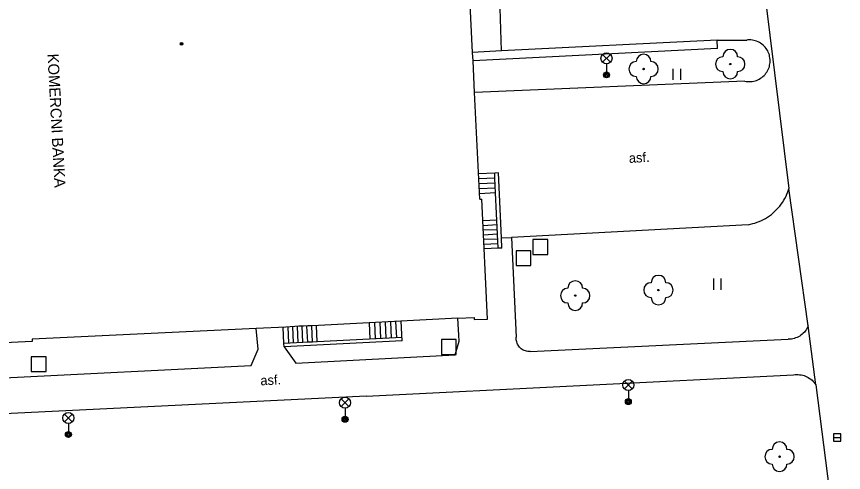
# Model space of a CAD drawing. Extents: x -641829 to -641525, y -1114855 to -1114359.
# Drawn here: x -641782.2 to -641726.2, y -1114487.2 to -1114456.3 of the extents above; entities that cross this region are included whole.
import ezdxf

# ---------------------------------------------------------------- set-up
doc = ezdxf.new("R2010")
doc.units = 0
for name, color, linetype in [('Vrstva 10', 7, 'Continuous'), ('Vrstva 11', 7, 'Continuous'), ('Vrstva 22', 7, 'Continuous'), ('Vrstva 26', 7, 'Continuous'), ('Vrstva 27', 7, 'Continuous'), ('Vrstva 33', 7, 'Continuous'), ('Vrstva 36', 7, 'Continuous'), ('Vrstva 39', 7, 'Continuous'), ('Vrstva 40', 7, 'Continuous'), ('Vrstva 41', 7, 'Continuous'), ('Vrstva 5', 7, 'Continuous')]:
    doc.layers.add(name, color=color, linetype=linetype)

msp = doc.modelspace()

# ---------------------------------------------------------------- linework, layer by layer
at = {"layer": 'Vrstva 10'}
for p, q in [((-641749.32, -1114458.63), (-641749.83, -1114441.84)), ((-641731.98, -1114450.77), (-641729.84, -1114467.94)), ((-641734.71, -1114457.89), (-641732.69, -1114457.89)), ((-641732.62, -1114457.88), (-641732.69, -1114457.89)), ((-641732.52, -1114457.88), (-641732.62, -1114457.88)), ((-641732.42, -1114457.88), (-641732.52, -1114457.88)), ((-641732.32, -1114457.9), (-641732.42, -1114457.88)), ((-641732.22, -1114457.91), (-641732.32, -1114457.9)), ((-641732.12, -1114457.94), (-641732.22, -1114457.91)), ((-641732.03, -1114457.97), (-641732.12, -1114457.94)), ((-641731.93, -1114458.01), (-641732.03, -1114457.97)), ((-641731.84, -1114458.06), (-641731.93, -1114458.01)), ((-641731.76, -1114458.11), (-641731.84, -1114458.06)), ((-641731.68, -1114458.17), (-641731.76, -1114458.11)), ((-641731.6, -1114458.23), (-641731.68, -1114458.17)), ((-641731.52, -1114458.3), (-641731.6, -1114458.23)), ((-641731.45, -1114458.37), (-641731.52, -1114458.3)), ((-641731.39, -1114458.45), (-641731.45, -1114458.37)), ((-641731.34, -1114458.53), (-641731.39, -1114458.45)), ((-641731.28, -1114458.62), (-641731.34, -1114458.53)), ((-641731.24, -1114458.71), (-641731.28, -1114458.62)), ((-641731.2, -1114458.81), (-641731.24, -1114458.71)), ((-641731.17, -1114458.9), (-641731.2, -1114458.81)), ((-641731.15, -1114459), (-641731.17, -1114458.9)), ((-641731.13, -1114459.1), (-641731.15, -1114459)), ((-641731.15, -1114459.6), (-641731.13, -1114459.5)), ((-641731.12, -1114459.2), (-641731.13, -1114459.1)), ((-641731.13, -1114459.5), (-641731.12, -1114459.4)), ((-641731.11, -1114459.3), (-641731.12, -1114459.2)), ((-641731.12, -1114459.4), (-641731.11, -1114459.3)), ((-641731.4, -1114460.14), (-641731.34, -1114460.06)), ((-641731.34, -1114460.06), (-641731.29, -1114459.98)), ((-641731.29, -1114459.98), (-641731.24, -1114459.89)), ((-641731.24, -1114459.89), (-641731.2, -1114459.79)), ((-641731.2, -1114459.79), (-641731.17, -1114459.7)), ((-641731.17, -1114459.7), (-641731.15, -1114459.6)), ((-641732.23, -1114460.67), (-641732.14, -1114460.65)), ((-641732.14, -1114460.65), (-641732.04, -1114460.62)), ((-641732.04, -1114460.62), (-641731.95, -1114460.58)), ((-641731.95, -1114460.58), (-641731.86, -1114460.53)), ((-641731.86, -1114460.53), (-641731.77, -1114460.48)), ((-641731.77, -1114460.48), (-641731.69, -1114460.43)), ((-641731.69, -1114460.43), (-641731.61, -1114460.36)), ((-641731.61, -1114460.36), (-641731.53, -1114460.3)), ((-641731.53, -1114460.3), (-641731.46, -1114460.22)), ((-641731.46, -1114460.22), (-641731.4, -1114460.14)), ((-641732.83, -1114460.67), (-641751.14, -1114461.43)), ((-641732.83, -1114460.67), (-641732.73, -1114460.69)), ((-641732.73, -1114460.69), (-641732.63, -1114460.7)), ((-641732.63, -1114460.7), (-641732.53, -1114460.7)), ((-641732.53, -1114460.7), (-641732.43, -1114460.7)), ((-641732.43, -1114460.7), (-641732.33, -1114460.69)), ((-641732.33, -1114460.69), (-641732.23, -1114460.67)), ((-641729.87, -1114468.02), (-641729.84, -1114467.94)), ((-641728.54, -1114477.24), (-641729.84, -1114467.94)), ((-641730.12, -1114468.61), (-641730.04, -1114468.46)), ((-641730.04, -1114468.46), (-641729.98, -1114468.32)), ((-641729.98, -1114468.32), (-641729.92, -1114468.17)), ((-641729.92, -1114468.17), (-641729.87, -1114468.02)), ((-641730.47, -1114469.13), (-641730.37, -1114469.01)), ((-641730.37, -1114469.01), (-641730.28, -1114468.88)), ((-641730.28, -1114468.88), (-641730.19, -1114468.74)), ((-641730.19, -1114468.74), (-641730.12, -1114468.61)), ((-641731.03, -1114469.69), (-641730.91, -1114469.59)), ((-641730.91, -1114469.59), (-641730.79, -1114469.48)), ((-641730.79, -1114469.48), (-641730.68, -1114469.37)), ((-641730.68, -1114469.37), (-641730.57, -1114469.25)), ((-641730.57, -1114469.25), (-641730.47, -1114469.13)), ((-641732, -1114470.23), (-641731.85, -1114470.17)), ((-641731.85, -1114470.17), (-641731.7, -1114470.11)), ((-641731.7, -1114470.11), (-641731.56, -1114470.03)), ((-641731.56, -1114470.03), (-641731.42, -1114469.96)), ((-641731.42, -1114469.96), (-641731.29, -1114469.87)), ((-641731.29, -1114469.87), (-641731.16, -1114469.78)), ((-641731.16, -1114469.78), (-641731.03, -1114469.69)), ((-641732.61, -1114470.39), (-641748.63, -1114471.25)), ((-641732.61, -1114470.39), (-641732.45, -1114470.36)), ((-641732.45, -1114470.36), (-641732.3, -1114470.32)), ((-641732.3, -1114470.32), (-641732.15, -1114470.28)), ((-641732.15, -1114470.28), (-641732, -1114470.23)), ((-641749.32, -1114471.28), (-641748.63, -1114471.25)), ((-641728.02, -1114481.24), (-641728.54, -1114477.24)), ((-641728.02, -1114481.24), (-641726.15, -1114495.75))]:
    msp.add_line(p, q, dxfattribs=at)
at = {"layer": 'Vrstva 11'}
for p, q in [((-641734.71, -1114457.89), (-641749.32, -1114458.63)), ((-641734.68, -1114458.45), (-641734.71, -1114457.89)), ((-641749.32, -1114458.63), (-641751.27, -1114458.73)), ((-641734.68, -1114458.45), (-641751.24, -1114459.29)), ((-641749.76, -1114467.23), (-641750.85, -1114467.28)), ((-641749.32, -1114471.28), (-641749.52, -1114466.88)), ((-641749.74, -1114467.57), (-641750.83, -1114467.62)), ((-641749.73, -1114467.91), (-641750.82, -1114467.96)), ((-641749.71, -1114468.24), (-641750.8, -1114468.3)), ((-641749.62, -1114470.09), (-641750.57, -1114470.14)), ((-641749.61, -1114470.41), (-641750.56, -1114470.46)), ((-641749.59, -1114470.73), (-641750.54, -1114470.77)), ((-641749.58, -1114471.04), (-641750.53, -1114471.09)), ((-641749.29, -1114471.98), (-641749.32, -1114471.28)), ((-641748.63, -1114471.25), (-641748.31, -1114478.01)), ((-641749.56, -1114471.36), (-641750.51, -1114471.4)), ((-641749.55, -1114471.68), (-641750.5, -1114471.72)), ((-641752.21, -1114477.87), (-641752.28, -1114476.73)), ((-641765.79, -1114478.81), (-641765.94, -1114477.42)), ((-641763.72, -1114478.42), (-641763.77, -1114477.31)), ((-641763.4, -1114478.4), (-641763.45, -1114477.29)), ((-641763.08, -1114478.39), (-641763.13, -1114477.28)), ((-641762.76, -1114478.37), (-641762.81, -1114477.26)), ((-641762.44, -1114478.35), (-641762.49, -1114477.25)), ((-641762.12, -1114478.34), (-641762.17, -1114477.23)), ((-641761.8, -1114478.32), (-641761.85, -1114477.21)), ((-641758.2, -1114478.14), (-641758.26, -1114477.03)), ((-641757.84, -1114478.12), (-641757.9, -1114477.01)), ((-641757.48, -1114478.1), (-641757.54, -1114477)), ((-641757.13, -1114478.09), (-641757.18, -1114476.98)), ((-641756.77, -1114478.07), (-641756.82, -1114476.96)), ((-641756.41, -1114478.05), (-641756.47, -1114476.94)), ((-641756.04, -1114478.26), (-641756.11, -1114476.92)), ((-641728.63, -1114477.42), (-641728.68, -1114477.5)), ((-641728.58, -1114477.33), (-641728.63, -1114477.42)), ((-641728.54, -1114477.24), (-641728.58, -1114477.33)), ((-641752.19, -1114478.27), (-641752.21, -1114477.87)), ((-641748.31, -1114478.1), (-641748.31, -1114478.01)), ((-641729.29, -1114478.02), (-641729.39, -1114478.06)), ((-641729.2, -1114477.98), (-641729.29, -1114478.02)), ((-641729.11, -1114477.93), (-641729.2, -1114477.98)), ((-641729.03, -1114477.87), (-641729.11, -1114477.93)), ((-641728.95, -1114477.81), (-641729.03, -1114477.87)), ((-641728.88, -1114477.74), (-641728.95, -1114477.81)), ((-641728.8, -1114477.67), (-641728.88, -1114477.74)), ((-641728.74, -1114477.59), (-641728.8, -1114477.67)), ((-641728.68, -1114477.5), (-641728.74, -1114477.59)), ((-641756.04, -1114478.26), (-641764.03, -1114478.67)), ((-641752.45, -1114479.2), (-641752.19, -1114478.27)), ((-641748.31, -1114478.18), (-641748.31, -1114478.1)), ((-641748.3, -1114478.25), (-641748.31, -1114478.18)), ((-641748.28, -1114478.33), (-641748.3, -1114478.25)), ((-641748.25, -1114478.41), (-641748.28, -1114478.33)), ((-641748.22, -1114478.48), (-641748.25, -1114478.41)), ((-641748.18, -1114478.55), (-641748.22, -1114478.48)), ((-641748.14, -1114478.62), (-641748.18, -1114478.55)), ((-641747.37, -1114478.98), (-641729.89, -1114478.15)), ((-641729.78, -1114478.15), (-641729.89, -1114478.15)), ((-641729.68, -1114478.14), (-641729.78, -1114478.15)), ((-641729.58, -1114478.12), (-641729.68, -1114478.14)), ((-641729.48, -1114478.09), (-641729.58, -1114478.12)), ((-641729.39, -1114478.06), (-641729.48, -1114478.09)), ((-641766.27, -1114479.92), (-641765.79, -1114478.81)), ((-641764.03, -1114478.67), (-641763.25, -1114479.76)), ((-641748.09, -1114478.68), (-641748.14, -1114478.62)), ((-641748.03, -1114478.74), (-641748.09, -1114478.68)), ((-641747.97, -1114478.79), (-641748.03, -1114478.74)), ((-641747.91, -1114478.84), (-641747.97, -1114478.79)), ((-641747.84, -1114478.88), (-641747.91, -1114478.84)), ((-641747.77, -1114478.91), (-641747.84, -1114478.88)), ((-641747.69, -1114478.94), (-641747.77, -1114478.91)), ((-641747.61, -1114478.96), (-641747.69, -1114478.94)), ((-641747.53, -1114478.97), (-641747.61, -1114478.96)), ((-641747.45, -1114478.98), (-641747.53, -1114478.97)), ((-641747.37, -1114478.98), (-641747.45, -1114478.98)), ((-641763.25, -1114479.76), (-641752.45, -1114479.2)), ((-641798.58, -1114481.55), (-641766.27, -1114479.92)), ((-641758.49, -1114482), (-641729.54, -1114480.56)), ((-641729.54, -1114480.56), (-641729.42, -1114480.54)), ((-641729.42, -1114480.54), (-641729.32, -1114480.54)), ((-641729.32, -1114480.54), (-641729.22, -1114480.54)), ((-641729.22, -1114480.54), (-641729.12, -1114480.55)), ((-641729.12, -1114480.55), (-641729.01, -1114480.56)), ((-641729.01, -1114480.56), (-641728.91, -1114480.58)), ((-641728.91, -1114480.58), (-641728.81, -1114480.61)), ((-641728.81, -1114480.61), (-641728.72, -1114480.65)), ((-641728.72, -1114480.65), (-641728.62, -1114480.69)), ((-641728.62, -1114480.69), (-641728.53, -1114480.74)), ((-641728.53, -1114480.74), (-641728.45, -1114480.8)), ((-641728.45, -1114480.8), (-641728.36, -1114480.86)), ((-641728.36, -1114480.86), (-641728.28, -1114480.92)), ((-641728.28, -1114480.92), (-641728.21, -1114481)), ((-641728.21, -1114481), (-641728.14, -1114481.07)), ((-641728.14, -1114481.07), (-641728.08, -1114481.15)), ((-641728.08, -1114481.15), (-641728.02, -1114481.24)), ((-641758.49, -1114482), (-641797.98, -1114483.93))]:
    msp.add_line(p, q, dxfattribs=at)
for points in [[(-641749.52, -1114466.88), (-641749.77, -1114466.9), (-641750.87, -1114466.95)], [(-641749.54, -1114471.99), (-641749.58, -1114471.04), (-641749.71, -1114468.24), (-641749.76, -1114467.23), (-641749.77, -1114466.9)], [(-641749.29, -1114471.98), (-641749.54, -1114471.99), (-641750.48, -1114472.03)], [(-641764.03, -1114478.67), (-641764.05, -1114478.44), (-641764.1, -1114477.33)], [(-641756.05, -1114478.03), (-641761.8, -1114478.32), (-641762.12, -1114478.34), (-641762.44, -1114478.35), (-641762.76, -1114478.37), (-641764.05, -1114478.44)]]:
    msp.add_lwpolyline(points, dxfattribs=at)
at = {"layer": 'Vrstva 22'}
for centre in [(-641733.82, -1114459.52), (-641739.69, -1114459.85), (-641744.32, -1114475.19), (-641738.68, -1114474.82), (-641730.48, -1114486.1)]:
    msp.add_circle(centre, 0.05, dxfattribs=at)
for centre, start, end in [((-641739.69, -1114459.35), 0, 180), ((-641733.82, -1114459.02), 0, 180), ((-641740.19, -1114459.85), 90, 270), ((-641739.19, -1114459.85), 270, 90), ((-641734.32, -1114459.52), 90, 270), ((-641733.32, -1114459.52), 270, 90), ((-641733.82, -1114460.02), 180, 0), ((-641739.69, -1114460.35), 180, 0), ((-641738.68, -1114474.32), 0, 180), ((-641744.32, -1114474.69), 0, 180), ((-641739.18, -1114474.82), 90, 270), ((-641738.18, -1114474.82), 270, 90), ((-641744.82, -1114475.19), 90, 270), ((-641743.82, -1114475.19), 270, 90), ((-641744.32, -1114475.69), 180, 0), ((-641738.68, -1114475.32), 180, 0), ((-641730.48, -1114485.6), 0, 180), ((-641730.98, -1114486.1), 90, 270), ((-641729.98, -1114486.1), 270, 90), ((-641730.48, -1114486.6), 180, 0)]:
    msp.add_arc(centre, 0.5, start, end, dxfattribs=at)
at = {"layer": 'Vrstva 26'}
for points in [[(-641747.18, -1114472.4), (-641746.18, -1114472.4), (-641746.18, -1114471.4), (-641747.18, -1114471.4)], [(-641748.33, -1114473.15), (-641747.33, -1114473.15), (-641747.33, -1114472.15), (-641748.33, -1114472.15)], [(-641753.38, -1114479.17), (-641752.38, -1114479.17), (-641752.38, -1114478.17), (-641753.38, -1114478.17)], [(-641781.16, -1114480.33), (-641780.16, -1114480.33), (-641780.16, -1114479.33), (-641781.16, -1114479.33)]]:
    msp.add_lwpolyline(points, close=True, dxfattribs=at)
at = {"layer": 'Vrstva 27'}
msp.add_line((-641726.83, -1114484.8), (-641726.33, -1114484.8), dxfattribs=at)
msp.add_lwpolyline([(-641726.83, -1114485.05), (-641726.33, -1114485.05), (-641726.33, -1114484.55), (-641726.83, -1114484.55)], close=True, dxfattribs=at)
at = {"layer": 'Vrstva 33'}
for p, q in [((-641742.464, -1114459.39), (-641741.936, -1114458.86)), ((-641742.464, -1114458.86), (-641741.936, -1114459.39)), ((-641742.2, -1114459.5), (-641742.2, -1114460.25)), ((-641740.986, -1114481.51), (-641740.454, -1114480.98)), ((-641740.986, -1114480.98), (-641740.454, -1114481.51)), ((-641740.72, -1114481.62), (-641740.72, -1114482.37)), ((-641760.176, -1114482.71), (-641759.644, -1114482.18)), ((-641760.176, -1114482.18), (-641759.644, -1114482.71)), ((-641759.91, -1114482.82), (-641759.91, -1114483.57)), ((-641778.914, -1114483.74), (-641778.386, -1114483.21)), ((-641778.914, -1114483.21), (-641778.386, -1114483.74)), ((-641778.65, -1114483.85), (-641778.65, -1114484.6))]:
    msp.add_line(p, q, dxfattribs=at)
for centre, radius in [((-641742.2, -1114459.125), 0.375), ((-641742.2, -1114460.25), 0.2), ((-641742.2, -1114460.25), 0.145), ((-641742.2, -1114460.25), 0.0876), ((-641740.72, -1114481.245), 0.375), ((-641759.91, -1114482.445), 0.375), ((-641740.72, -1114482.37), 0.2), ((-641740.72, -1114482.37), 0.145), ((-641740.72, -1114482.37), 0.0876), ((-641778.65, -1114483.475), 0.375), ((-641759.91, -1114483.57), 0.2), ((-641759.91, -1114483.57), 0.145), ((-641759.91, -1114483.57), 0.0876), ((-641778.65, -1114484.6), 0.2), ((-641778.65, -1114484.6), 0.145), ((-641778.65, -1114484.6), 0.0876)]:
    msp.add_circle(centre, radius, dxfattribs=at)
at = {"layer": 'Vrstva 36'}
for p, q in [((-641737.674, -1114460.582), (-641737.674, -1114459.834)), ((-641737.174, -1114460.582), (-641737.174, -1114459.834)), ((-641734.924, -1114474.794), (-641734.924, -1114474.042)), ((-641734.424, -1114474.794), (-641734.424, -1114474.042))]:
    msp.add_line(p, q, dxfattribs=at)
at = {"layer": 'Vrstva 39'}
for radius in [0.09, 0.0398]:
    msp.add_circle((-641770.98, -1114458.14), radius, dxfattribs=at)
at = {"layer": 'Vrstva 5'}
for p, q in [((-641751.27, -1114458.73), (-641752.17, -1114440.22)), ((-641751.24, -1114459.29), (-641751.27, -1114458.73)), ((-641751.14, -1114461.43), (-641751.24, -1114459.29)), ((-641750.78, -1114468.67), (-641751.14, -1114461.43)), ((-641750.78, -1114468.67), (-641750.64, -1114468.66)), ((-641750.26, -1114476.78), (-641750.64, -1114468.66)), ((-641752.28, -1114476.73), (-641762.13, -1114477.23)), ((-641752.28, -1114476.73), (-641751.17, -1114476.68)), ((-641751.17, -1114476.68), (-641751.16, -1114476.82)), ((-641751.16, -1114476.82), (-641750.26, -1114476.78)), ((-641765.94, -1114477.42), (-641781.11, -1114478.15)), ((-641763.92, -1114477.32), (-641765.94, -1114477.42)), ((-641763.62, -1114477.3), (-641763.92, -1114477.32)), ((-641763.32, -1114477.29), (-641763.62, -1114477.3)), ((-641763.03, -1114477.27), (-641763.32, -1114477.29)), ((-641762.73, -1114477.26), (-641763.03, -1114477.27)), ((-641762.43, -1114477.24), (-641762.73, -1114477.26)), ((-641762.13, -1114477.23), (-641762.43, -1114477.24)), ((-641781.11, -1114478.29), (-641788.04, -1114478.65)), ((-641781.11, -1114478.15), (-641781.11, -1114478.29))]:
    msp.add_line(p, q, dxfattribs=at)

# ---------------------------------------------------------------- texts
at = {"layer": 'Vrstva 40'}
for rotation, p in [(3.0721, (-641740.67, -1114466.21)), (2.7981, (-641765.63, -1114481.27))]:
    msp.add_text('asf.', height=0.65, rotation=rotation, dxfattribs=at).set_placement(p)
at = {"layer": 'Vrstva 41'}
msp.add_text('KOMERCNI BANKA', height=0.75, rotation=273.0404, dxfattribs=at).set_placement((-641780.07, -1114458.83))

doc.saveas('drawing.dxf')
